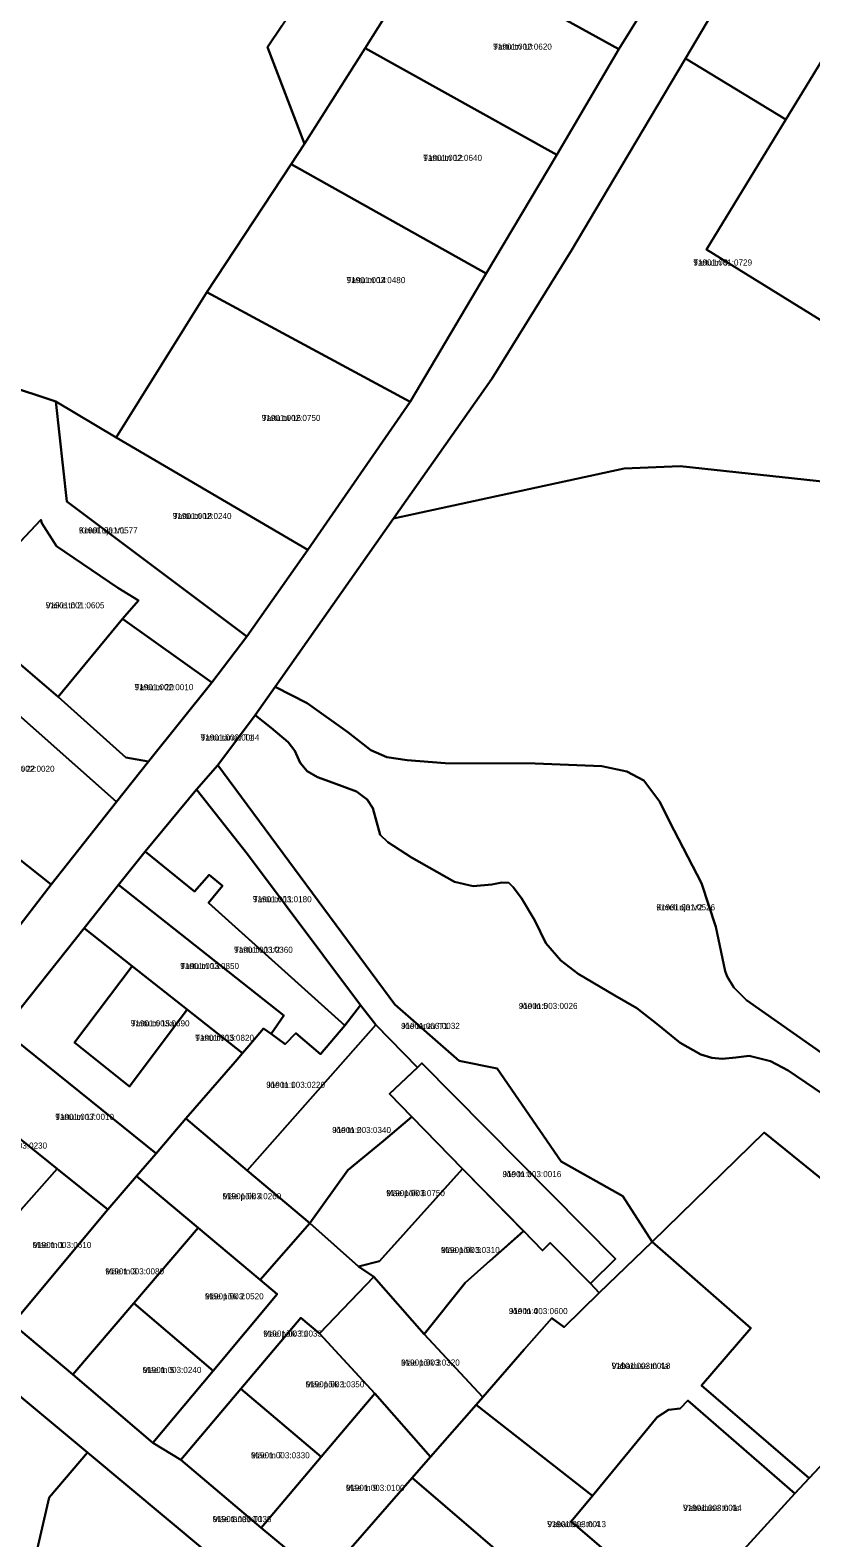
# Model space of a CAD drawing. Extents: x 675810 to 681273, y 6411190 to 6417565.
# Drawn here: x 678007 to 678199.8, y 6415777.9 to 6416150.4 of the extents above; entities that cross this region are included whole.
import ezdxf

# ---------------------------------------------------------------- set-up
doc = ezdxf.new("R2010")
doc.units = 0
for name, color, linetype in [('L_AADRESS', 7, 'Continuous'), ('PIIR', 7, 'Continuous'), ('TUNNUS', 7, 'Continuous')]:
    doc.layers.add(name, color=color, linetype=linetype)

msp = doc.modelspace()

# ---------------------------------------------------------------- linework, layer by layer
at = {"layer": 'PIIR'}
for points in [[(677850.92, 6415745.75), (677892.37, 6415795.81), (677892.68, 6415798.34), (677906.28, 6415805.64), (677919.87, 6415822.87), (677949.83, 6415860.06), (677977.79, 6415894.52), (677991.85, 6415913.02), (678012.12, 6415939.38), (678028.34, 6415959.8), (678036.2, 6415969.78), (678051.83, 6415989.26), (678060.52, 6416000.64), (678075.54, 6416022.07), (678100.87, 6416058.58), (678119.65, 6416090.34), (678137.06, 6416119.67), (678152.43, 6416145.77), (678168.3, 6416171.4), (678194.05, 6416216.28), (678203.85, 6416235.23)], [(678069.12, 6416151.53), (678065.57, 6416146.25), (678074.72, 6416122.37), (678071.49, 6416117.3), (678050.59, 6416085.71), (678028.23, 6416049.84), (678013.3, 6416058.67), (678000.61, 6416062.93), (677999.55, 6416066.69), (677993.5, 6416088.08), (677983.33, 6416124.07), (677973.55, 6416196.97)], [(678175.49, 6416154.58), (678168.87, 6416143.42), (678149.69, 6416111.17), (678140.78, 6416096.13), (678121.02, 6416064.26), (678096.76, 6416029.81), (678068.87, 6415990.17), (678067.47, 6415988.2), (678062.57, 6415981.16), (678053.32, 6415968.87), (678048.05, 6415962.82), (678035.41, 6415947.52), (678028.79, 6415939.24), (678020.29, 6415928.58), (678000.32, 6415903.37), (677988.75, 6415889.13), (677980.25, 6415878.63), (677965.38, 6415860.08), (677958.32, 6415851.32), (677924.58, 6415808.71), (677914.14, 6415795.53), (677900.77, 6415778.51), (677886.97, 6415760.95)], [(678203.33, 6415897.16), (678183.97, 6415910.77), (678180.78, 6415913.95), (678179.19, 6415916.65), (678178.69, 6415917.98), (678176.35, 6415928.91), (678172.81, 6415939.65), (678164.95, 6415954.93), (678162.56, 6415959.76), (678158.61, 6415965.06), (678154.36, 6415967.31), (678148.19, 6415968.59), (678131.71, 6415969.27), (678109.48, 6415969.37), (678100.08, 6415970.1), (678095.11, 6415970.82), (678091.14, 6415972.58), (678085.47, 6415977), (678075.42, 6415984.2), (678067.47, 6415988.2), (678068.87, 6415990.17), (678096.76, 6416029.81), (678153.73, 6416042.11), (678167.55, 6416042.69), (678234.74, 6416035.48)], [(678168.13, 6415758.41), (678195.91, 6415788.86), (678199.44, 6415792.68), (678240.19, 6415836.05), (678254.64, 6415851.22), (678260.81, 6415857.94), (678262.55, 6415859.81), (678308.11, 6415908.8), (678390.84, 6415998.47), (678422.39, 6416032.66)], [(678207.13, 6415884.69), (678194.27, 6415893.4), (678189.85, 6415895.73), (678184.64, 6415897), (678181.28, 6415896.61), (678177.93, 6415896.27), (678175.39, 6415896.54), (678172.68, 6415897.36), (678167.56, 6415900.23), (678161.8, 6415904.95), (678156.82, 6415908.79), (678151.38, 6415911.91), (678142.39, 6415917.31), (678138.1, 6415920.57), (678134.37, 6415924.9), (678131.64, 6415930.5), (678128.32, 6415936), (678126.29, 6415938.72), (678125.23, 6415939.75), (678123.53, 6415939.84), (678120.99, 6415939.4), (678116.43, 6415938.91), (678111.82, 6415939.98), (678101.22, 6415946.02), (678095.37, 6415949.86), (678093.43, 6415951.61), (678091.67, 6415958.23), (678090.24, 6415960.38), (678087.57, 6415962.37), (678081.85, 6415964.46), (678077.94, 6415965.92), (678075.4, 6415967.38), (678073.69, 6415969.42), (678072.4, 6415972.39), (678070.69, 6415974.54), (678066.5, 6415978.09), (678062.57, 6415981.16), (678067.47, 6415988.2), (678075.42, 6415984.2), (678085.47, 6415977), (678091.14, 6415972.58), (678095.11, 6415970.82), (678100.08, 6415970.1), (678109.48, 6415969.37), (678131.71, 6415969.27), (678148.19, 6415968.59), (678154.36, 6415967.31), (678158.61, 6415965.06), (678162.56, 6415959.76), (678164.95, 6415954.93), (678172.81, 6415939.65), (678176.35, 6415928.91), (678178.69, 6415917.98), (678179.19, 6415916.65), (678180.78, 6415913.95), (678183.97, 6415910.77), (678203.33, 6415897.16)], [(678240.19, 6415836.05), (678188.28, 6415878.11), (678160.66, 6415851.04), (678153.38, 6415862.35), (678138.2, 6415870.94), (678122.32, 6415893.93), (678112.93, 6415895.78), (678097.03, 6415909.75), (678053.32, 6415968.87), (678062.57, 6415981.16), (678066.5, 6415978.09), (678070.69, 6415974.54), (678072.4, 6415972.39), (678073.69, 6415969.42), (678075.4, 6415967.38), (678077.94, 6415965.92), (678081.85, 6415964.46), (678087.57, 6415962.37), (678090.24, 6415960.38), (678091.67, 6415958.23), (678093.43, 6415951.61), (678095.37, 6415949.86), (678101.22, 6415946.02), (678111.82, 6415939.98), (678116.43, 6415938.91), (678120.99, 6415939.4), (678123.53, 6415939.84), (678125.23, 6415939.75), (678126.29, 6415938.72), (678128.32, 6415936), (678131.64, 6415930.5), (678134.37, 6415924.9), (678138.1, 6415920.57), (678142.39, 6415917.31), (678151.38, 6415911.91), (678156.82, 6415908.79), (678161.8, 6415904.95), (678167.56, 6415900.23), (678172.68, 6415897.36), (678175.39, 6415896.54), (678177.93, 6415896.27), (678181.28, 6415896.61), (678184.64, 6415897), (678189.85, 6415895.73), (678194.27, 6415893.4), (678207.13, 6415884.69)]]:
    msp.add_lwpolyline(points, dxfattribs=at)
for points in [[(678123.38, 6416195.98), (678107.69, 6416170.46), (678105.83, 6416171.59), (678089.76, 6416145.97), (678074.72, 6416122.37), (678065.57, 6416146.25), (678069.12, 6416151.53), (678109.48, 6416211.6), (678126.34, 6416200.97)], [(678123.38, 6416195.98), (678151.33, 6416180.68), (678168.3, 6416171.4), (678152.43, 6416145.77), (678107.69, 6416170.46)], [(678137.06, 6416119.67), (678089.76, 6416145.97), (678105.83, 6416171.59), (678107.69, 6416170.46), (678152.43, 6416145.77)], [(678193.66, 6416128.36), (678168.87, 6416143.42), (678175.49, 6416154.58), (678186.28, 6416172.5), (678189.4, 6416173.09), (678212.72, 6416159.63), (678211.28, 6416157.32), (678200.41, 6416139.44)], [(678211.28, 6416157.32), (678293.17, 6416109.13), (678269.42, 6416067.84), (678266.58, 6416038.96), (678244.88, 6416052.4), (678174.04, 6416096.22), (678193.66, 6416128.36), (678200.41, 6416139.44)], [(678071.49, 6416117.3), (678074.72, 6416122.37), (678089.76, 6416145.97), (678137.06, 6416119.67), (678119.65, 6416090.34)], [(678096.76, 6416029.81), (678121.02, 6416064.26), (678140.78, 6416096.13), (678149.69, 6416111.17), (678168.87, 6416143.42), (678193.66, 6416128.36), (678174.04, 6416096.22), (678244.88, 6416052.4), (678234.74, 6416035.48), (678167.55, 6416042.69), (678153.73, 6416042.11)], [(677855.02, 6416128.1), (677876.19, 6416108.9), (677880.28, 6416105.23), (677901.47, 6416086.09), (677913.5, 6416075.11), (677937.04, 6416053.74), (677947.61, 6416043.45), (677961.42, 6416029.94), (677966.5, 6416028.67), (677967.51, 6416026.41), (677988.99, 6416006.94), (678013.9, 6415985.76), (678030.61, 6415970.76), (678036.2, 6415969.78), (678028.34, 6415959.8), (677988.51, 6415995.01), (677973.85, 6416008.84), (677959.08, 6416022.35), (677945.09, 6416034.95), (677932.24, 6416046.12), (677911.66, 6416064.53), (677864.29, 6416106.93), (677854.1, 6416116.05)], [(678071.49, 6416117.3), (678119.65, 6416090.34), (678100.87, 6416058.58), (678050.59, 6416085.71)], [(678028.23, 6416049.84), (678050.59, 6416085.71), (678100.87, 6416058.58), (678075.54, 6416022.07)], [(678029.76, 6416004.96), (678033.74, 6416009.55), (678028.6, 6416012.62), (678013.51, 6416022.98), (678009.87, 6416028.6), (678009.6, 6416029.44), (678004.5, 6416024.04), (678000.61, 6416062.93), (678013.3, 6416058.67), (678016.01, 6416034.02), (678060.52, 6416000.64), (678051.83, 6415989.26)], [(678028.23, 6416049.84), (678075.54, 6416022.07), (678060.52, 6416000.64), (678016.01, 6416034.02), (678013.3, 6416058.67)], [(678028.6, 6416012.62), (678033.74, 6416009.55), (678029.76, 6416004.96), (678013.9, 6415985.76), (677988.99, 6416006.94), (678004.5, 6416024.04), (678009.6, 6416029.44), (678009.87, 6416028.6), (678013.51, 6416022.98)], [(678030.61, 6415970.76), (678013.9, 6415985.76), (678029.76, 6416004.96), (678051.83, 6415989.26), (678036.2, 6415969.78)], [(678012.12, 6415939.38), (677969.24, 6415973.37), (677988.51, 6415995.01), (678028.34, 6415959.8)], [(677991.85, 6415913.02), (677947.2, 6415948.25), (677960.48, 6415963.4), (677969.24, 6415973.37), (678012.12, 6415939.38)], [(678048.05, 6415962.82), (678053.32, 6415968.87), (678097.03, 6415909.75), (678112.93, 6415895.78), (678122.32, 6415893.93), (678138.2, 6415870.94), (678153.38, 6415862.35), (678160.66, 6415851.04), (678147.56, 6415838.49), (678145.37, 6415840.76), (678151.62, 6415846.91), (678103.73, 6415895.21), (678102.64, 6415894.18), (678092.33, 6415904.67), (678088.62, 6415909.57), (678060.64, 6415946.88)], [(678048.05, 6415962.82), (678060.64, 6415946.88), (678088.62, 6415909.57), (678084.7, 6415904.5), (678051.02, 6415934.8), (678054.51, 6415939.04), (678051.17, 6415941.77), (678047.57, 6415937.66), (678035.41, 6415947.52)], [(678028.79, 6415939.24), (678035.41, 6415947.52), (678047.57, 6415937.66), (678051.17, 6415941.77), (678054.51, 6415939.04), (678051.02, 6415934.8), (678084.7, 6415904.5), (678078.71, 6415897.47), (678072.61, 6415902.6), (678069.96, 6415899.9), (678066.5, 6415902.43), (678069.64, 6415906.99)], [(678059.42, 6415897.72), (678045.77, 6415908.48), (678032.21, 6415919.15), (678020.29, 6415928.58), (678028.79, 6415939.24), (678069.64, 6415906.99), (678066.5, 6415902.43), (678064.65, 6415903.79), (678060.98, 6415899.53)], [(678032.21, 6415919.15), (678017.93, 6415900.33), (678031.5, 6415889.48), (678045.77, 6415908.48), (678059.42, 6415897.72), (678057.59, 6415895.58), (678045.47, 6415881.52), (678038.06, 6415872.91), (678000.32, 6415903.37), (678020.29, 6415928.58)], [(678045.77, 6415908.48), (678031.5, 6415889.48), (678017.93, 6415900.33), (678032.21, 6415919.15)], [(678060.58, 6415868.67), (678045.47, 6415881.52), (678057.59, 6415895.58), (678059.42, 6415897.72), (678060.98, 6415899.53), (678064.65, 6415903.79), (678066.5, 6415902.43), (678069.96, 6415899.9), (678072.61, 6415902.6), (678078.71, 6415897.47), (678084.7, 6415904.5), (678088.62, 6415909.57), (678092.33, 6415904.67)], [(678038.06, 6415872.91), (678033.23, 6415867.29), (678026.12, 6415859.03), (678013.65, 6415869.08), (677988.75, 6415889.13), (678000.32, 6415903.37)], [(678060.58, 6415868.67), (678092.33, 6415904.67), (678102.64, 6415894.18), (678095.75, 6415887.65), (678101.26, 6415881.95), (678094.23, 6415876.01), (678085.49, 6415868.79), (678076.04, 6415855.68)], [(678103.73, 6415895.21), (678151.62, 6415846.91), (678145.37, 6415840.76), (678135.46, 6415850.84), (678133.54, 6415848.93), (678128.84, 6415853.76), (678114.38, 6415868.57), (678113.82, 6415869.13), (678101.26, 6415881.95), (678095.75, 6415887.65), (678102.64, 6415894.18)], [(678013.65, 6415869.08), (678004.72, 6415859.09), (677980.25, 6415878.63), (677988.75, 6415889.13)], [(678045.47, 6415881.52), (678060.58, 6415868.67), (678076.04, 6415855.68), (678063.81, 6415841.7), (678048.48, 6415854.54), (678033.23, 6415867.29), (678038.06, 6415872.91)], [(678076.04, 6415855.68), (678085.49, 6415868.79), (678094.23, 6415876.01), (678101.26, 6415881.95), (678113.82, 6415869.13), (678093.31, 6415846.32), (678088.12, 6415845.02)], [(678188.28, 6415878.11), (678240.19, 6415836.05), (678199.44, 6415792.68), (678172.86, 6415815.56), (678185.03, 6415829.76), (678160.66, 6415851.04)], [(677989.04, 6415841.04), (678004.72, 6415859.09), (678013.65, 6415869.08), (678026.12, 6415859.03), (678002.6, 6415830.83)], [(678114.48, 6415840.93), (678104.34, 6415828.27), (678091.86, 6415842.39), (678088.12, 6415845.02), (678093.31, 6415846.32), (678113.82, 6415869.13), (678114.38, 6415868.57), (678128.83, 6415853.75), (678120.56, 6415846.36)], [(678002.6, 6415830.83), (678026.12, 6415859.03), (678033.23, 6415867.29), (678048.48, 6415854.54), (678032.56, 6415835.93), (678017.49, 6415818.31)], [(677958.32, 6415851.32), (677965.38, 6415860.08), (677989.04, 6415841.04), (678002.6, 6415830.83), (678017.49, 6415818.31), (678037.27, 6415801.42), (678044.16, 6415797.19), (678064.02, 6415780.43), (678079.45, 6415767.67), (678122.48, 6415731.92), (678137.13, 6415719.66), (678127.15, 6415703.55), (678101.05, 6415725.55), (678072.26, 6415749.82), (678047.39, 6415770.78), (678050.54, 6415774.48), (678021.12, 6415799.06), (677988.86, 6415825.89)], [(678063.81, 6415841.7), (678068, 6415838.12), (678052.16, 6415819.19), (678032.56, 6415835.93), (678048.48, 6415854.54)], [(678076.04, 6415855.68), (678088.12, 6415845.02), (678091.86, 6415842.39), (678078.45, 6415828.44), (678073.87, 6415832.32), (678059.02, 6415814.75), (678044.16, 6415797.19), (678037.27, 6415801.42), (678052.16, 6415819.19), (678068, 6415838.12), (678063.81, 6415841.7)], [(678118.77, 6415812.68), (678104.34, 6415828.27), (678114.48, 6415840.93), (678120.56, 6415846.36), (678128.84, 6415853.76), (678133.54, 6415848.93), (678135.46, 6415850.83), (678145.37, 6415840.76), (678147.56, 6415838.49), (678138.9, 6415829.99), (678135.86, 6415832.25), (678129.05, 6415824.47)], [(678117.15, 6415810.82), (678118.77, 6415812.68), (678129.05, 6415824.47), (678135.86, 6415832.25), (678138.9, 6415829.99), (678147.56, 6415838.49), (678160.66, 6415851.04), (678185.03, 6415829.76), (678172.86, 6415815.56), (678199.44, 6415792.68), (678195.91, 6415788.86), (678169.47, 6415811.87), (678167.52, 6415809.86), (678164.68, 6415809.53), (678161.91, 6415807.79), (678145.86, 6415788.34)], [(678117.15, 6415810.82), (678105.89, 6415797.97), (678092.14, 6415813.6), (678078.45, 6415828.44), (678091.86, 6415842.39), (678104.34, 6415828.27), (678118.77, 6415812.68)], [(678032.56, 6415835.93), (678052.16, 6415819.19), (678037.27, 6415801.42), (678017.49, 6415818.31)], [(678059.02, 6415814.75), (678073.87, 6415832.32), (678078.45, 6415828.44), (678092.14, 6415813.6), (678078.87, 6415797.95)], [(678021.12, 6415799.06), (678011.66, 6415787.93), (678008.2, 6415772.88), (678003.37, 6415767.17), (677999.09, 6415771.21), (677986.81, 6415756.9), (677955.66, 6415782.78), (677988.86, 6415825.89)], [(678059.02, 6415814.75), (678078.87, 6415797.95), (678064.02, 6415780.43), (678044.16, 6415797.19)], [(678064.02, 6415780.43), (678078.87, 6415797.95), (678092.14, 6415813.6), (678105.89, 6415797.97), (678101.32, 6415792.73), (678079.45, 6415767.67)], [(678117.15, 6415810.82), (678145.86, 6415788.34), (678140.65, 6415781.96), (678168.13, 6415758.41), (678155.55, 6415744.9), (678142.57, 6415755.89), (678143.29, 6415756.75), (678101.32, 6415792.73), (678105.89, 6415797.97)], [(678169.47, 6415811.87), (678195.91, 6415788.86), (678168.13, 6415758.41), (678140.65, 6415781.96), (678145.86, 6415788.34), (678161.91, 6415807.79), (678164.68, 6415809.53), (678167.52, 6415809.86)], [(678050.54, 6415774.48), (678047.39, 6415770.78), (678032.53, 6415752.94), (678024.14, 6415759.81), (678008.2, 6415772.88), (678011.66, 6415787.93), (678021.12, 6415799.06)], [(678101.32, 6415792.73), (678143.29, 6415756.75), (678122.48, 6415731.92), (678079.45, 6415767.67)]]:
    msp.add_lwpolyline(points, close=True, dxfattribs=at)

# ---------------------------------------------------------------- texts
at = {"layer": 'L_AADRESS'}
for s, p in [('Tartu tn 10', (678121.36, 6416145.63)), ('Tartu tn 12', (678104.1, 6416118.15)), ('Tartu tn 9', (678170.82, 6416092.29)), ('Tartu tn 14', (678085.15, 6416087.94)), ('Tartu tn 16', (678064.19, 6416053.89)), ('Tartu tn 18', (678042.22, 6416029.66)), ('Koreli oja V1', (678019.03, 6416026.1)), ('Väike tn 2', (678010.82, 6416007.6)), ('Tartu tn 20', (678032.77, 6415987.37)), ('Tartu tänav T1', (678049.09, 6415974.93)), ('Tartu tn 22', (677998.5, 6415967.2)), ('Tartu tn 11', (678062.01, 6415934.98)), ('Koreli oja V2', (678161.69, 6415932.98)), ('Tartu tn 11/2', (678057.35, 6415922.49)), ('Tartu tn 13', (678044.07, 6415918.48)), ('Jõe tn 5', (678127.7, 6415908.61)), ('Tartu tn 15a', (678031.85, 6415904.31)), ('Tartu tn 15', (678047.77, 6415900.74)), ('Jõe tänav T1', (678098.62, 6415903.68)), ('Jõe tn 1', (678065.32, 6415889.12)), ('Tartu tn 17', (678013.19, 6415881.2)), ('Jõe tn 2', (678081.61, 6415877.96)), ('Jõe tn 3', (678123.68, 6415867.06)), ('Mäe põik 4', (678054.5, 6415861.61)), ('Mäe põik 6', (678094.93, 6415862.36)), ('Mäe tn 1', (678007.58, 6415849.55)), ('Mäe põik 5', (678108.47, 6415848.31)), ('Mäe tn 3', (678025.54, 6415843.03)), ('Mäe põik 2', (678050.15, 6415836.87)), ('Jõe tn 4', (678125.25, 6415833.22)), ('Mäe põik T1', (678064.57, 6415827.66)), ('Mäe tn 5', (678034.77, 6415818.68)), ('Mäe põik 3', (678098.61, 6415820.5)), ('Vabaduse tn 4a', (678150.64, 6415819.69)), ('Mäe põik 1', (678075.03, 6415815.13)), ('Mäe tn 7', (678061.53, 6415797.59)), ('Mäe tn 9', (678084.96, 6415789.55)), ('Mäe tänav T1', (678052.07, 6415781.82)), ('Vabaduse tn 4c', (678168.28, 6415784.61)), ('Vabaduse tn 4', (678134.73, 6415780.58))]:
    msp.add_text(s, height=1.5, dxfattribs=at).set_placement(p)
at = {"layer": 'TUNNUS'}
for s, p in [('91901:002:0620', (678121.36, 6416145.63)), ('91901:002:0640', (678104.1, 6416118.15)), ('91901:001:0729', (678170.82, 6416092.29)), ('91901:002:0480', (678085.15, 6416087.94)), ('91901:002:0750', (678064.19, 6416053.89)), ('91901:002:0240', (678042.22, 6416029.66)), ('91901:001:0577', (678019.03, 6416026.1)), ('91901:001:0605', (678010.82, 6416007.6)), ('91901:002:0010', (678032.77, 6415987.37)), ('91901:002:0044', (678049.09, 6415974.93)), ('91901:002:0020', (677998.5, 6415967.2)), ('91901:003:0180', (678062.01, 6415934.98)), ('91901:001:0526', (678161.69, 6415932.98)), ('91901:003:0360', (678057.35, 6415922.49)), ('91901:003:0850', (678044.07, 6415918.48)), ('91901:003:0026', (678127.7, 6415908.61)), ('91901:003:0690', (678031.85, 6415904.31)), ('91901:003:0820', (678047.77, 6415900.74)), ('91901:003:0032', (678098.62, 6415903.68)), ('91901:003:0220', (678065.32, 6415889.12)), ('91901:003:0010', (678013.19, 6415881.2)), ('91901:003:0340', (678081.61, 6415877.96)), ('91901:003:0230', (677996.66, 6415874.11)), ('91901:003:0016', (678123.68, 6415867.06)), ('91901:003:0260', (678054.5, 6415861.61)), ('91901:003:0750', (678094.93, 6415862.36)), ('91901:003:0610', (678007.58, 6415849.55)), ('91901:003:0310', (678108.47, 6415848.31)), ('91901:003:0080', (678025.54, 6415843.03)), ('91901:003:0520', (678050.15, 6415836.87)), ('91901:003:0600', (678125.25, 6415833.22)), ('91901:003:0033', (678064.57, 6415827.66)), ('91901:003:0240', (678034.77, 6415818.68)), ('91901:003:0320', (678098.61, 6415820.5)), ('91901:003:0018', (678150.64, 6415819.69)), ('91901:003:0350', (678075.03, 6415815.13)), ('91901:003:0330', (678061.53, 6415797.59)), ('91901:003:0100', (678084.96, 6415789.55)), ('91901:003:0035', (678052.07, 6415781.82)), ('91901:003:0014', (678168.28, 6415784.61)), ('91901:003:0013', (678134.73, 6415780.58))]:
    msp.add_text(s, height=1.5, dxfattribs=at).set_placement(p)

doc.saveas('drawing.dxf')
